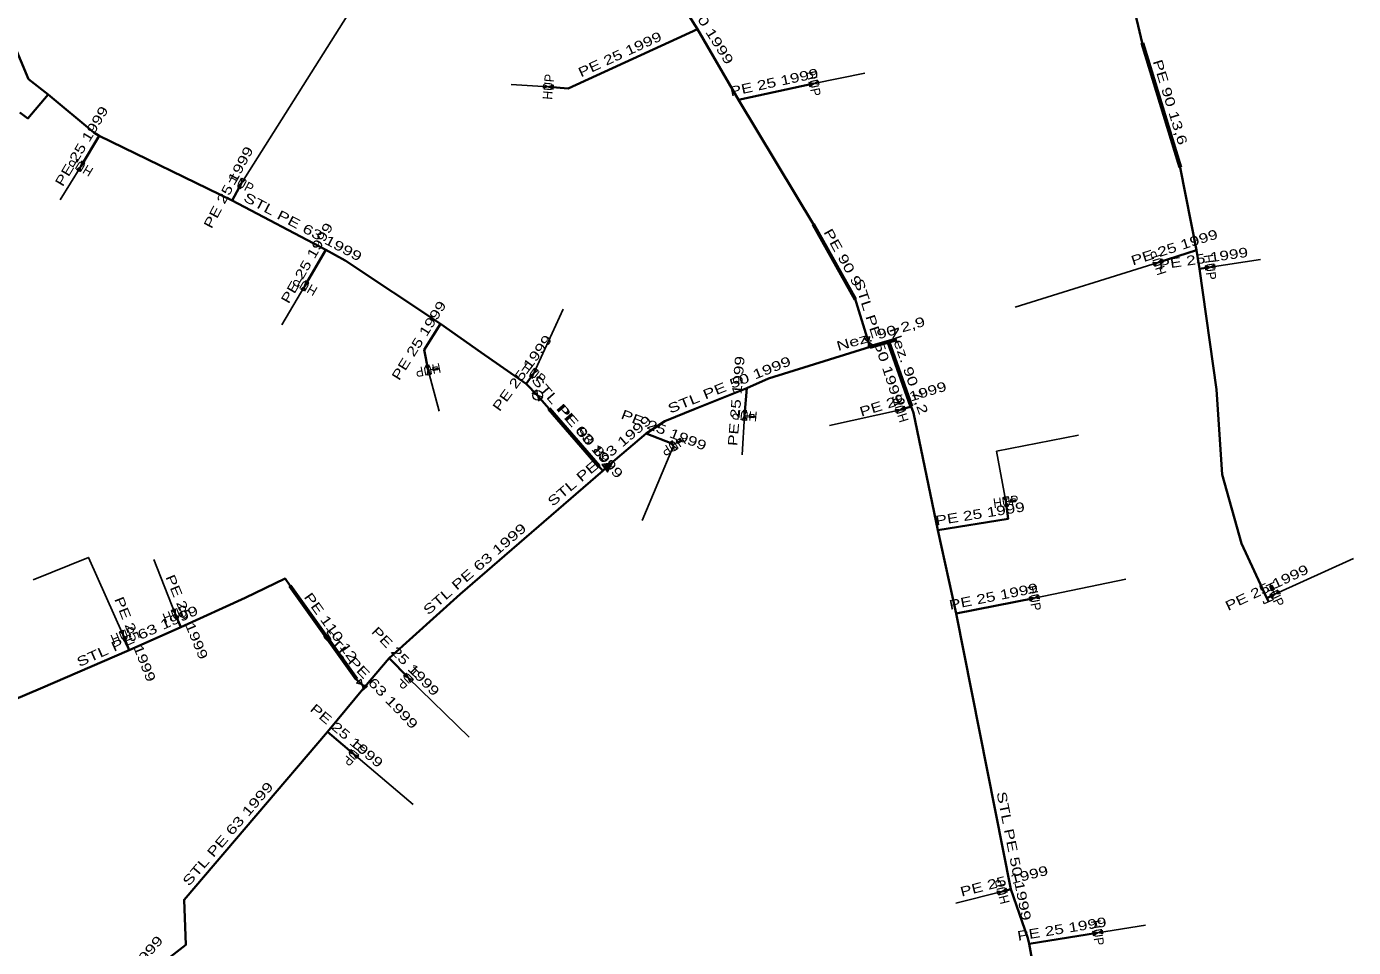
# Model space of a CAD drawing. Extents: x -737484 to -734496, y -1033882 to -1030666.
# Drawn here: x -736219.6 to -736080.7, y -1032296.4 to -1032200 of the extents above; entities that cross this region are included whole.
import ezdxf
from ezdxf.enums import TextEntityAlignment as Align

# ---------------------------------------------------------------- set-up
doc = ezdxf.new("R2010")
doc.units = 0
doc.header["$LTSCALE"] = 0.4
for name, color, linetype, lineweight in [('1', 7, 'Continuous', 13), ('18', 7, 'Continuous', 60), ('22', 7, 'Continuous', 25), ('5', 7, 'Continuous', 35), ('7', 7, 'Continuous', 35)]:
    doc.layers.add(name, color=color, linetype=linetype, lineweight=lineweight)
doc.layers.add('2', color=7, linetype='Continuous')

msp = doc.modelspace()

# ---------------------------------------------------------------- linework, layer by layer
at = {"layer": '1'}
for p, q in [((-736177.549, -1032235.987), (-736177.058, -1032235.891)), ((-736176.97, -1032235.95), (-736176.626, -1032235.884)), ((-736144.429, -1032240.739), (-736143.93, -1032240.782)), ((-736143.862, -1032240.863), (-736143.514, -1032240.894)), ((-736151.927, -1032243.814), (-736151.502, -1032243.549)), ((-736151.399, -1032243.572), (-736151.102, -1032243.387)), ((-736117.079, -1032249.749), (-736116.583, -1032249.679)), ((-736116.499, -1032249.743), (-736116.152, -1032249.694)), ((-736089.104, -1032258.896), (-736089.251, -1032258.578)), ((-736088.929, -1032259.449), (-736089.14, -1032258.995))]:
    msp.add_line(p, q, dxfattribs=at)
for points in [[(-736165.464, -1032206.484), (-736165.429, -1032206.086), (-736164.468, -1032206.571), (-736164.433, -1032206.173)], [(-736136.741, -1032205.687), (-736136.658, -1032206.078), (-736137.719, -1032205.895), (-736137.636, -1032206.286)], [(-736213.995, -1032215.191), (-736214.337, -1032214.985), (-736213.48, -1032214.334), (-736213.822, -1032214.128)], [(-736197.03, -1032215.891), (-736196.677, -1032216.079), (-736197.5, -1032216.774), (-736197.147, -1032216.962)], [(-736101.56, -1032225.064), (-736101.684, -1032224.684), (-736100.609, -1032224.755), (-736100.733, -1032224.375)], [(-736095.251, -1032224.94), (-736095.196, -1032225.336), (-736096.241, -1032225.079), (-736096.186, -1032225.475)], [(-736190.526, -1032227.702), (-736190.873, -1032227.502), (-736190.026, -1032226.835), (-736190.373, -1032226.635)], [(-736131.92, -1032232.706), (-736131.368, -1032232.472), (-736131.529, -1032233.627), (-736130.977, -1032233.393)], [(-736177.255, -1032236.439), (-736177.647, -1032236.515), (-736177.446, -1032235.458), (-736177.838, -1032235.534)], [(-736176.567, -1032235.796), (-736176.595, -1032235.648), (-736177.086, -1032235.744), (-736177.058, -1032235.891)], [(-736176.567, -1032235.796), (-736176.538, -1032235.943), (-736177.029, -1032236.038), (-736177.058, -1032235.891)], [(-736176.597, -1032235.839), (-736176.583, -1032235.913), (-736177, -1032235.994), (-736177.014, -1032235.92)], [(-736166.356, -1032235.795), (-736166.033, -1032236.031), (-736166.944, -1032236.604), (-736166.621, -1032236.84)], [(-736166.643, -1032238.447), (-736166.19, -1032238.053), (-736165.987, -1032239.202), (-736165.534, -1032238.808)], [(-736128.527, -1032240.467), (-736128.644, -1032240.084), (-736127.571, -1032240.175), (-736127.688, -1032239.792)], [(-736144.272, -1032241.255), (-736144.67, -1032241.22), (-736144.185, -1032240.259), (-736144.583, -1032240.224)], [(-736143.432, -1032240.826), (-736143.445, -1032240.975), (-736143.943, -1032240.932), (-736143.93, -1032240.782)], [(-736143.432, -1032240.826), (-736143.419, -1032240.676), (-736143.917, -1032240.633), (-736143.93, -1032240.782)], [(-736143.473, -1032240.859), (-736143.48, -1032240.934), (-736143.903, -1032240.897), (-736143.897, -1032240.822)], [(-736151.434, -1032244.225), (-736151.773, -1032244.437), (-736151.964, -1032243.376), (-736152.303, -1032243.588)], [(-736151.078, -1032243.284), (-736151.158, -1032243.156), (-736151.582, -1032243.421), (-736151.502, -1032243.549)], [(-736151.078, -1032243.284), (-736150.999, -1032243.411), (-736151.423, -1032243.676), (-736151.502, -1032243.549)], [(-736151.091, -1032243.335), (-736151.051, -1032243.399), (-736151.412, -1032243.624), (-736151.451, -1032243.56)], [(-736159.355, -1032245.869), (-736158.767, -1032246.678), (-736158.252, -1032245.686)], [(-736158.781, -1032246.488), (-736158.433, -1032245.817), (-736159.179, -1032245.941)], [(-736158.614, -1032245.948), (-736159.003, -1032246.013), (-736158.795, -1032246.299)], [(-736117.346, -1032249.281), (-736116.95, -1032249.226), (-736117.207, -1032250.271), (-736116.811, -1032250.216)], [(-736116.088, -1032249.609), (-736116.109, -1032249.461), (-736116.604, -1032249.53), (-736116.583, -1032249.679)], [(-736116.088, -1032249.609), (-736116.067, -1032249.758), (-736116.562, -1032249.827), (-736116.583, -1032249.679)], [(-736116.121, -1032249.651), (-736116.11, -1032249.726), (-736116.531, -1032249.785), (-736116.542, -1032249.71)], [(-736113.657, -1032259.547), (-736113.581, -1032259.939), (-736114.638, -1032259.738), (-736114.562, -1032260.13)], [(-736089.351, -1032258.542), (-736089.487, -1032258.606), (-736089.276, -1032259.059), (-736089.14, -1032258.995)], [(-736088.561, -1032259.057), (-736088.392, -1032259.419), (-736089.467, -1032259.48), (-736089.298, -1032259.842)], [(-736089.351, -1032258.542), (-736089.215, -1032258.479), (-736089.004, -1032258.932), (-736089.14, -1032258.995)], [(-736089.302, -1032258.561), (-736089.234, -1032258.529), (-736089.054, -1032258.914), (-736089.122, -1032258.946)], [(-736204.381, -1032261.108), (-736204.01, -1032260.958), (-736204.007, -1032262.035), (-736203.636, -1032261.885)], [(-736209.82, -1032263.35), (-736209.449, -1032263.2), (-736209.446, -1032264.277), (-736209.075, -1032264.127)], [(-736179.127, -1032268.418), (-736179.415, -1032268.696), (-736179.822, -1032267.699), (-736180.11, -1032267.977)], [(-736185.032, -1032268.748), (-736184.6, -1032268.331), (-736184.337, -1032269.468), (-736183.905, -1032269.051)], [(-736184.827, -1032276.347), (-736185.084, -1032276.653), (-736185.593, -1032275.704), (-736185.85, -1032276.01)], [(-736117.904, -1032290.862), (-736118.001, -1032290.473), (-736116.934, -1032290.62), (-736117.031, -1032290.231)], [(-736107.017, -1032294.602), (-736106.954, -1032294.997), (-736108.005, -1032294.758), (-736107.942, -1032295.153)]]:
    msp.add_lwpolyline(points, close=True, dxfattribs=at)
msp.add_lwpolyline([(-736089.223, -1032259.807), (-736089.122, -1032260.035), (-736090.035, -1032260.442), (-736090.137, -1032260.213)], dxfattribs=at)
msp.add_circle((-736166.0893, -1032238.6278), 0.5, dxfattribs=at)
at = {"layer": '18'}
for p, q in [((-736102.829, -1032201.729), (-736098.852, -1032214.734)), ((-736132.814, -1032228.609), (-736137.204, -1032220.753)), ((-736131.289, -1032233.539), (-736128.503, -1032232.732)), ((-736129.389, -1032232.989), (-736127.001, -1032239.781)), ((-736164.919, -1032239.989), (-736159.676, -1032246.031)), ((-736192.035, -1032258.572), (-736185.059, -1032268.334))]:
    msp.add_line(p, q, dxfattribs=at)
at = {"layer": '22'}
for p, q in [((-736197.089, -1032216.427), (-736180.237, -1032189.737)), ((-736137.189, -1032205.988), (-736131.829, -1032204.887)), ((-736164.949, -1032206.329), (-736168.864, -1032206.075)), ((-736213.909, -1032214.66), (-736216.063, -1032218.157)), ((-736101.148, -1032224.72), (-736116.113, -1032229.394)), ((-736095.719, -1032225.209), (-736090.433, -1032224.396)), ((-736190.45, -1032227.169), (-736192.849, -1032231.23)), ((-736166.489, -1032236.319), (-736163.416, -1032229.62)), ((-736177.548, -1032235.988), (-736176.391, -1032240.296)), ((-736128.107, -1032240.13), (-736135.554, -1032241.797)), ((-736144.43, -1032240.74), (-736144.668, -1032244.862)), ((-736151.869, -1032243.908), (-736155.138, -1032251.734)), ((-736204.009, -1032261.498), (-736206.237, -1032255.808)), ((-736088.93, -1032259.45), (-736080.705, -1032255.711)), ((-736114.11, -1032259.838), (-736104.516, -1032257.852)), ((-736179.62, -1032268.199), (-736173.254, -1032274.399)), ((-736185.339, -1032276.179), (-736179.097, -1032281.459)), ((-736117.468, -1032290.547), (-736122.316, -1032291.772)), ((-736107.48, -1032294.879), (-736102.455, -1032294.089))]:
    msp.add_line(p, q, dxfattribs=at)
for points in [[(-736117.078, -1032249.749), (-736118.058, -1032244.473), (-736109.476, -1032242.801)], [(-736209.449, -1032263.739), (-736213.096, -1032255.594), (-736218.883, -1032257.952)]]:
    msp.add_lwpolyline(points, dxfattribs=at)
at = {"layer": '5'}
for p, q in [((-736131.449, -1032233.05), (-736131.29, -1032233.54)), ((-736158.657, -1032245.98), (-736159.28, -1032246.51)), ((-736184.22, -1032269.16), (-736184.469, -1032268.9))]:
    msp.add_line(p, q, dxfattribs=at)
for points in [[(-736127.074, -1032093.129), (-736125.39, -1032094.99), (-736121.45, -1032113.97), (-736118.08, -1032113.18), (-736114.16, -1032129.74), (-736113.45, -1032133.45), (-736113.75, -1032142.44), (-736113.83, -1032147.94), (-736112.8, -1032153.07), (-736108.44, -1032174.65), (-736104.7, -1032193.05), (-736103.84, -1032197.45), (-736102.83, -1032201.73), (-736098.84, -1032214.78), (-736097.14, -1032223.44), (-736096.83, -1032225.37), (-736095.05, -1032238.02), (-736094.44, -1032246.92), (-736092.43, -1032254.14), (-736089.76, -1032259.84), (-736089.579, -1032260.239)], [(-736171.5, -1032158.59), (-736177.9, -1032159.31), (-736177.95, -1032160.38), (-736178, -1032161.29), (-736180.93, -1032181.4), (-736182.02, -1032182.19), (-736191.9, -1032182.29), (-736206.46, -1032181.97), (-736206.89, -1032181.97), (-736209.11, -1032182.68), (-736213.27, -1032184.68), (-736213.59, -1032184.82), (-736214.83, -1032186.32), (-736220.36, -1032193.6), (-736222.02, -1032198.72), (-736221.95, -1032199.37), (-736219.36, -1032205.52), (-736217.3, -1032207.13)], [(-736169.19, -1032163.86), (-736165.2, -1032173.06), (-736153.88, -1032193.1), (-736149.35, -1032200.29), (-736145.08, -1032207.68), (-736137.14, -1032220.84), (-736132.88, -1032228.43), (-736131.449, -1032233.05)], [(-736220.27, -1032209.02), (-736219.43, -1032209.64), (-736217.3, -1032207.13)], [(-736217.3, -1032207.13), (-736212.52, -1032211.12), (-736211.99, -1032211.45), (-736198.04, -1032218.22), (-736188.27, -1032223.38), (-736186.23, -1032224.52), (-736176.24, -1032231.13), (-736172, -1032234.13), (-736167.3, -1032237.43), (-736166.089, -1032238.628)], [(-736103.84, -1032342.71), (-736107.29, -1032330.35), (-736109.04, -1032322.62), (-736110.11, -1032320.93), (-736111.31, -1032315.44), (-736113.32, -1032303.09), (-736113.48, -1032302.39), (-736114.65, -1032296.04), (-736114.78, -1032295.45), (-736116.57, -1032290.32), (-736122.27, -1032261.46), (-736124.19, -1032252.73), (-736126.74, -1032240.47), (-736127, -1032239.79), (-736129.39, -1032232.99), (-736131.29, -1032233.54)], [(-736131.29, -1032233.54), (-736141.91, -1032236.86), (-736144.19, -1032237.86), (-736149.59, -1032240.03), (-736152.77, -1032241.33), (-736154.72, -1032242.61), (-736158.657, -1032245.98)], [(-736166.089, -1032238.628), (-736164.92, -1032239.99), (-736159.68, -1032246.03), (-736159.28, -1032246.51)], [(-736159.28, -1032246.51), (-736174.19, -1032259.44), (-736181.64, -1032266.12), (-736184.22, -1032269.16)], [(-736184.469, -1032268.9), (-736185, -1032268.42), (-736191.98, -1032258.58), (-736192.51, -1032257.8), (-736196.69, -1032259.82), (-736203.43, -1032262.9), (-736208.83, -1032265.3), (-736218.1, -1032269.3), (-736223.98, -1032271.79), (-736235.31, -1032276.96)], [(-736184.22, -1032269.16), (-736188.09, -1032273.85), (-736203.08, -1032291.43), (-736202.89, -1032296.13), (-736208.68, -1032300.64), (-736209.15, -1032301.16)]]:
    msp.add_lwpolyline(points, dxfattribs=at)
at = {"layer": '7'}
for p, q in [((-736145.08, -1032207.68), (-736137.189, -1032205.987)), ((-736211.99, -1032211.45), (-736213.909, -1032214.66)), ((-736198.04, -1032218.22), (-736197.089, -1032216.427)), ((-736188.27, -1032223.38), (-736190.45, -1032227.169)), ((-736097.14, -1032223.44), (-736101.147, -1032224.72)), ((-736096.83, -1032225.37), (-736095.719, -1032225.208)), ((-736167.3, -1032237.43), (-736166.489, -1032236.318)), ((-736144.19, -1032237.86), (-736144.428, -1032240.74)), ((-736127, -1032239.79), (-736128.108, -1032240.13)), ((-736089.76, -1032259.84), (-736088.93, -1032259.45)), ((-736122.27, -1032261.46), (-736114.11, -1032259.839)), ((-736203.43, -1032262.9), (-736204.009, -1032261.497)), ((-736208.83, -1032265.3), (-736209.448, -1032263.739)), ((-736181.64, -1032266.12), (-736179.619, -1032268.198)), ((-736188.09, -1032273.85), (-736185.339, -1032276.179)), ((-736116.57, -1032290.32), (-736117.468, -1032290.547)), ((-736114.65, -1032296.04), (-736107.48, -1032294.878))]:
    msp.add_line(p, q, dxfattribs=at)
for points in [[(-736149.35, -1032200.29), (-736162.88, -1032206.51), (-736164.949, -1032206.329)], [(-736176.24, -1032231.13), (-736177.95, -1032233.87), (-736177.547, -1032235.987)], [(-736154.72, -1032242.61), (-736152.03, -1032243.65), (-736151.869, -1032243.907)], [(-736124.19, -1032252.73), (-736116.84, -1032251.55), (-736117.079, -1032249.749)]]:
    msp.add_lwpolyline(points, dxfattribs=at)

# ---------------------------------------------------------------- texts
at = {"layer": '18'}
for s, rotation, width, p in [('PE 90 13,6', 287.004, 1.4, (-736100.3616, -1032208.0853)), ('PE 90 9', 299.197, 1.4, (-736134.572, -1032224.4361)), ('Nez. 90 2,9', 16.154, 1.4, (-736130.0351, -1032232.6548)), ('Nez. 90 7,2', 289.371, 1.4, (-736127.7228, -1032236.2182)), ('PE 90 8', 310.95, 1.4, (-736161.9193, -1032242.6813)), ('PE 110 12', 305.55, 1.35, (-736188.1389, -1032263.1623))]:
    msp.add_text(s, height=1, rotation=rotation, dxfattribs=dict(at, width=width)).set_placement(p, align=Align.CENTER)
at = {"layer": '2', "width": 0.95}
for rotation, p in [(85, (-736164.4503, -1032206.3721)), (282, (-736137.6772, -1032206.0905)), (149, (-736213.651, -1032214.2308)), (332, (-736197.3232, -1032216.868)), (108, (-736100.671, -1032224.565)), (278, (-736096.2133, -1032225.2769)), (150, (-736190.1995, -1032226.7359)), (191, (-736177.6421, -1032235.4961)), (324, (-736166.7824, -1032236.722)), (175, (-736144.3839, -1032240.2413)), (107, (-736127.6288, -1032239.9837)), (212, (-736152.1335, -1032243.4823)), (8, (-736117.0091, -1032250.2433)), (295, (-736089.3824, -1032259.6602)), (281, (-736114.5999, -1032259.9341)), (22, (-736203.8208, -1032261.96)), (22, (-736209.2598, -1032264.202)), (224, (-736179.9652, -1032267.8374)), (230, (-736185.7216, -1032275.8571)), (104, (-736116.982, -1032290.4255)), (279, (-736107.9735, -1032294.9553))]:
    msp.add_text('HUP', height=1, rotation=rotation, dxfattribs=at).set_placement(p, align=Align.CENTER)
at = {"layer": '5', "width": 1.4}
for s, rotation, p in [('STL PE 50 1999', 302.213, (-736150.0182, -1032198.29)), ('STL PE 63 1999', 332.159, (-736190.8875, -1032221.4316)), ('STL PE 50 1999', 287.978, (-736130.8935, -1032233.1397)), ('STL PE 50 1999', 21.893, (-736145.8389, -1032237.9837)), ('STL PE 63 1999', 310.943, (-736162.3048, -1032242.2398)), ('STL PE 63 1999', 40.389, (-736159.292, -1032245.8642)), ('STL PE 63 1999', 40.932, (-736172.3481, -1032257.1807)), ('STL PE 63 1999', 23.962, (-736207.7766, -1032264.2841)), ('STL PE 63 1999', 313.762, (-736183.9831, -1032268.6842)), ('STL PE 63 1999', 49.547, (-736198.1269, -1032284.8504)), ('STL PE 50 1999', 281.172, (-736116.7267, -1032286.9416)), ('STL PE 63 1999', 49.803, (-736209.64, -1032300.9657))]:
    msp.add_text(s, height=1, rotation=rotation, dxfattribs=at).set_placement(p, align=Align.CENTER)
at = {"layer": '7', "width": 1.35}
for rotation, p in [(24.689, (-736157.2668, -1032203.3786)), (12.109, (-736141.2389, -1032206.3443)), (59.128, (-736213.3786, -1032212.7981)), (62.059, (-736198.0055, -1032217.0888)), (60.086, (-736189.7927, -1032225.0243)), (17.716, (-736099.2956, -1032223.6027)), (8.296, (-736096.3461, -1032224.7935)), (58.032, (-736178.0892, -1032233.1487)), (53.896, (-736167.2982, -1032236.5786)), (85.276, (-736144.8068, -1032239.2582)), (17.059, (-736127.7002, -1032239.4812)), (338.863, (-736153.0528, -1032242.7176)), (9.121, (-736119.6968, -1032251.5023)), (25.168, (-736089.5576, -1032259.1921)), (292.425, (-736203.2574, -1032262.0068)), (11.236, (-736118.2869, -1032260.1589)), (291.599, (-736208.6735, -1032264.3349)), (314.203, (-736180.27, -1032266.8104)), (319.749, (-736186.3911, -1032274.633)), (14.186, (-736117.141, -1032289.9478)), (9.206, (-736111.1445, -1032294.9652))]:
    msp.add_text('PE 25 1999', height=1, rotation=rotation, dxfattribs=at).set_placement(p, align=Align.CENTER)

doc.saveas('drawing.dxf')
